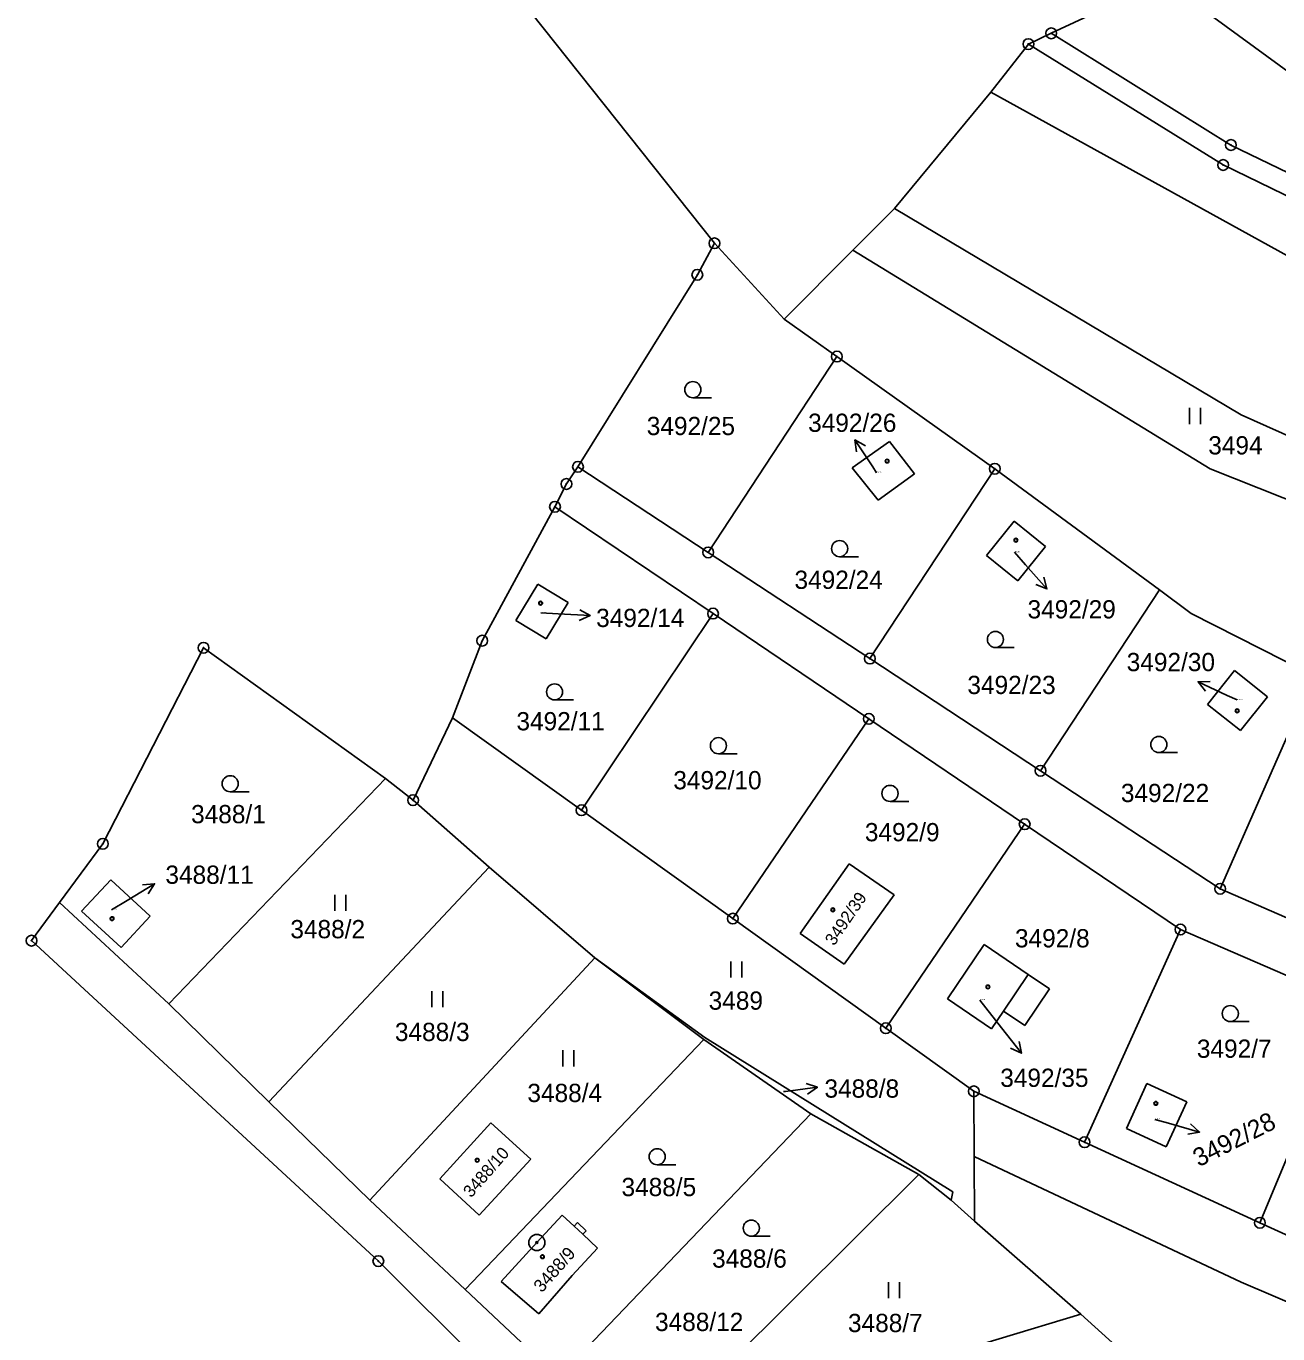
# Model space of a CAD drawing. Extents: x -593183 to -588034, y -1130415 to -1124994.
# Drawn here: x -592836.2 to -592719.7, y -1129035.2 to -1128913.5 of the extents above; entities that cross this region are included whole.
import ezdxf

# ---------------------------------------------------------------- set-up
doc = ezdxf.new("R2010")
doc.units = 0
for name, color, linetype in [('Vrstva 1', 7, 'Continuous'), ('Vrstva 16', 7, 'Continuous'), ('Vrstva 18', 7, 'Continuous'), ('Vrstva 19', 7, 'Continuous'), ('Vrstva 24', 7, 'Continuous'), ('Vrstva 25', 7, 'Continuous'), ('Vrstva 4', 7, 'Continuous')]:
    doc.layers.add(name, color=color, linetype=linetype)

msp = doc.modelspace()

# ---------------------------------------------------------------- linework, layer by layer
at = {"layer": 'Vrstva 1'}
for p, q in [((-592792.9, -1128907.62), (-592772.18, -1128933.7)), ((-592730.37, -1128909.25), (-592740.83, -1128914.15)), ((-592730.37, -1128909.25), (-592713.31, -1128921.75)), ((-592740.83, -1128914.15), (-592742.96, -1128915.15)), ((-592740.83, -1128914.15), (-592724.11, -1128924.55)), ((-592746.46, -1128919.64), (-592742.96, -1128915.15)), ((-592742.96, -1128915.15), (-592724.83, -1128926.41)), ((-592755.43, -1128930.45), (-592746.46, -1128919.64)), ((-592746.46, -1128919.64), (-592718.85, -1128934.87)), ((-592724.11, -1128924.55), (-592695.06, -1128938.62)), ((-592724.83, -1128926.41), (-592695.79, -1128940.49)), ((-592759.3, -1128934.34), (-592755.43, -1128930.45)), ((-592755.43, -1128930.45), (-592723.17, -1128949.66)), ((-592772.18, -1128933.7), (-592773.77, -1128936.63)), ((-592772.18, -1128933.7), (-592765.68, -1128940.75)), ((-592765.68, -1128940.75), (-592759.3, -1128934.34)), ((-592759.3, -1128934.34), (-592726.03, -1128954.69)), ((-592773.77, -1128936.63), (-592784.88, -1128954.51)), ((-592765.68, -1128940.75), (-592760.78, -1128944.25)), ((-592760.78, -1128944.25), (-592772.76, -1128962.48)), ((-592760.78, -1128944.25), (-592746.09, -1128954.69)), ((-592723.17, -1128949.66), (-592691.23, -1128964.05)), ((-592755.89, -1128952.17), (-592759.37, -1128954.61)), ((-592753.55, -1128955.16), (-592755.89, -1128952.17)), ((-592784.88, -1128954.51), (-592785.96, -1128956.11)), ((-592772.76, -1128962.48), (-592784.88, -1128954.51)), ((-592759.37, -1128954.61), (-592756.95, -1128957.63)), ((-592746.09, -1128954.69), (-592757.71, -1128972.37)), ((-592746.09, -1128954.69), (-592730.76, -1128965.97)), ((-592726.03, -1128954.69), (-592694.14, -1128967.46)), ((-592756.95, -1128957.63), (-592753.55, -1128955.16)), ((-592787.02, -1128958.23), (-592785.96, -1128956.11)), ((-592793.79, -1128970.7), (-592787.02, -1128958.23)), ((-592787.02, -1128958.23), (-592772.31, -1128968.18)), ((-592746.85, -1128962.77), (-592744.27, -1128959.58)), ((-592744.27, -1128959.58), (-592741.36, -1128961.94)), ((-592741.36, -1128961.94), (-592743.93, -1128965.13)), ((-592757.71, -1128972.37), (-592772.76, -1128962.48)), ((-592743.93, -1128965.13), (-592746.85, -1128962.77)), ((-592788.62, -1128965.45), (-592790.65, -1128968.82)), ((-592785.8, -1128967.15), (-592788.62, -1128965.45)), ((-592730.76, -1128965.97), (-592741.83, -1128982.81)), ((-592730.76, -1128965.97), (-592727.81, -1128968.16)), ((-592787.83, -1128970.52), (-592785.8, -1128967.15)), ((-592790.65, -1128968.82), (-592787.83, -1128970.52)), ((-592772.31, -1128968.18), (-592784.55, -1128986.49)), ((-592772.31, -1128968.18), (-592757.81, -1128977.98)), ((-592727.81, -1128968.16), (-592716.41, -1128973.96)), ((-592829.1, -1128989.61), (-592819.73, -1128971.36)), ((-592819.73, -1128971.36), (-592802.81, -1128983.54)), ((-592793.79, -1128970.7), (-592796.57, -1128977.87)), ((-592741.83, -1128982.81), (-592757.71, -1128972.37)), ((-592726.28, -1128976.63), (-592723.78, -1128973.48)), ((-592716.41, -1128973.96), (-592725.11, -1128993.8)), ((-592723.78, -1128973.48), (-592720.71, -1128975.92)), ((-592723.21, -1128979.07), (-592726.28, -1128976.63)), ((-592720.71, -1128975.92), (-592723.21, -1128979.07)), ((-592800.23, -1128985.55), (-592796.57, -1128977.87)), ((-592796.57, -1128977.87), (-592784.55, -1128986.49)), ((-592757.81, -1128977.98), (-592770.47, -1128996.58)), ((-592757.81, -1128977.98), (-592743.31, -1128987.79)), ((-592802.81, -1128983.54), (-592822.97, -1129004.51)), ((-592802.81, -1128983.54), (-592800.23, -1128985.55)), ((-592741.83, -1128982.81), (-592725.11, -1128993.8)), ((-592800.23, -1128985.55), (-592793.15, -1128991.79)), ((-592784.55, -1128986.49), (-592770.47, -1128996.58)), ((-592743.31, -1128987.79), (-592756.23, -1129006.79)), ((-592743.31, -1128987.79), (-592728.81, -1128997.59)), ((-592833.15, -1128995.08), (-592829.1, -1128989.61)), ((-592813.65, -1129013.64), (-592793.15, -1128991.79)), ((-592793.15, -1128991.79), (-592783.3, -1129000.23)), ((-592764.2, -1128997.96), (-592759.64, -1128991.47)), ((-592759.64, -1128991.47), (-592755.44, -1128994.35)), ((-592831.08, -1128995.89), (-592828.37, -1128992.96)), ((-592828.37, -1128992.96), (-592824.7, -1128996.34)), ((-592755.44, -1128994.35), (-592760.11, -1129000.83)), ((-592725.11, -1128993.8), (-592708.62, -1129001.03)), ((-592833.15, -1128995.08), (-592835.74, -1128998.63)), ((-592822.97, -1129004.51), (-592833.15, -1128995.08)), ((-592827.39, -1128999.26), (-592831.08, -1128995.89)), ((-592824.7, -1128996.34), (-592827.39, -1128999.26)), ((-592770.47, -1128996.58), (-592756.23, -1129006.79)), ((-592760.11, -1129000.83), (-592764.2, -1128997.96)), ((-592737.73, -1129017.4), (-592728.81, -1128997.59)), ((-592728.81, -1128997.59), (-592712.93, -1129004.46)), ((-592835.74, -1128998.63), (-592803.46, -1129028.47)), ((-592750.5, -1129004.06), (-592747.08, -1128999)), ((-592747.08, -1128999), (-592742.97, -1129001.78)), ((-592783.3, -1129000.23), (-592804.24, -1129022.81)), ((-592773.16, -1129007.85), (-592783.3, -1129000.23)), ((-592783.3, -1129000.23), (-592773.06, -1129007.65)), ((-592742.97, -1129001.78), (-592740.99, -1129003.11)), ((-592740.99, -1129003.11), (-592743.29, -1129006.53)), ((-592822.97, -1129004.51), (-592813.65, -1129013.64)), ((-592746.38, -1129006.84), (-592750.5, -1129004.06)), ((-592712.93, -1129004.46), (-592721.41, -1129024.9)), ((-592745.27, -1129005.19), (-592746.38, -1129006.84)), ((-592743.29, -1129006.53), (-592745.27, -1129005.19)), ((-592756.23, -1129006.79), (-592748.04, -1129012.66)), ((-592795.38, -1129031.11), (-592773.16, -1129007.85)), ((-592773.16, -1129007.85), (-592763.22, -1129014.75)), ((-592773.06, -1129007.65), (-592750, -1129022.01)), ((-592733.84, -1129016.11), (-592731.93, -1129011.94)), ((-592731.93, -1129011.94), (-592728.21, -1129013.65)), ((-592748.04, -1129012.66), (-592737.73, -1129017.4)), ((-592748, -1129018.74), (-592748.04, -1129012.66)), ((-592804.24, -1129022.81), (-592813.65, -1129013.64)), ((-592728.21, -1129013.65), (-592730.13, -1129017.82)), ((-592797.75, -1129020.8), (-592792.98, -1129015.58)), ((-592792.98, -1129015.58), (-592789.27, -1129018.98)), ((-592763.22, -1129014.75), (-592786.68, -1129039.27)), ((-592763.22, -1129014.75), (-592753.15, -1129020.41)), ((-592730.13, -1129017.82), (-592733.84, -1129016.11)), ((-592737.73, -1129017.4), (-592721.41, -1129024.9)), ((-592789.27, -1129018.98), (-592794.07, -1129024.2)), ((-592748, -1129018.74), (-592747.99, -1129024.74)), ((-592748, -1129018.74), (-592723.17, -1129030.44)), ((-592778.43, -1129045.55), (-592753.15, -1129020.41)), ((-592753.15, -1129020.41), (-592750.15, -1129022.78)), ((-592794.07, -1129024.2), (-592797.75, -1129020.8)), ((-592804.24, -1129022.81), (-592795.38, -1129031.11)), ((-592750, -1129022.01), (-592750.15, -1129022.78)), ((-592750.15, -1129022.78), (-592747.99, -1129024.74)), ((-592788.71, -1129026.74), (-592786.34, -1129024.2)), ((-592786.34, -1129024.2), (-592785.24, -1129025.22)), ((-592785.24, -1129025.22), (-592784.94, -1129024.89)), ((-592784.94, -1129024.89), (-592784.13, -1129025.64)), ((-592747.99, -1129024.74), (-592738.08, -1129033.41)), ((-592704.97, -1129032.46), (-592721.41, -1129024.9)), ((-592784.13, -1129025.64), (-592784.44, -1129025.97)), ((-592784.44, -1129025.97), (-592783.05, -1129027.27)), ((-592788.71, -1129026.74), (-592792.02, -1129030.36)), ((-592783.05, -1129027.27), (-592785.42, -1129029.81)), ((-592803.46, -1129028.47), (-592784.63, -1129047.23)), ((-592788.54, -1129033.38), (-592785.42, -1129029.81)), ((-592786.68, -1129039.27), (-592795.38, -1129031.11)), ((-592792.02, -1129030.36), (-592788.54, -1129033.38)), ((-592723.17, -1129030.44), (-592709.6, -1129036.24)), ((-592738.08, -1129033.41), (-592778.43, -1129045.55)), ((-592738.08, -1129033.41), (-592734.83, -1129036.37))]:
    msp.add_line(p, q, dxfattribs=at)
at = {"layer": 'Vrstva 16'}
for p, q in [((-592757.09, -1128955.06), (-592757.45, -1128954.51)), ((-592744.25, -1128962.46), (-592743.22, -1128963.63)), ((-592788.33, -1128968.12), (-592786.74, -1128968.21)), ((-592723.52, -1128976.22), (-592724.45, -1128975.79)), ((-592828.29, -1128995.76), (-592826.85, -1128994.89)), ((-592747.48, -1129004.17), (-592745.46, -1129006.75)), ((-592765.75, -1129012.69), (-592765.57, -1129012.67)), ((-592731.19, -1129015.27), (-592729.92, -1129015.63))]:
    msp.add_line(p, q, dxfattribs=at)
at = {"layer": 'Vrstva 24'}
for centre, radius in [((-592740.83, -1128914.15), 0.5), ((-592740.83, -1128914.15), 0.0327), ((-592742.96, -1128915.15), 0.5), ((-592742.96, -1128915.15), 0.0327), ((-592724.11, -1128924.55), 0.5), ((-592724.11, -1128924.55), 0.0327), ((-592724.83, -1128926.41), 0.5), ((-592724.83, -1128926.41), 0.0327), ((-592772.18, -1128933.7), 0.5), ((-592772.18, -1128933.7), 0.0327), ((-592773.77, -1128936.63), 0.5), ((-592773.77, -1128936.63), 0.0327), ((-592760.78, -1128944.25), 0.5), ((-592760.78, -1128944.25), 0.0327), ((-592784.88, -1128954.51), 0.5), ((-592784.88, -1128954.51), 0.0327), ((-592746.09, -1128954.69), 0.5), ((-592746.09, -1128954.69), 0.0327), ((-592785.96, -1128956.11), 0.5), ((-592785.96, -1128956.11), 0.0327), ((-592787.02, -1128958.23), 0.5), ((-592787.02, -1128958.23), 0.0327), ((-592772.76, -1128962.48), 0.5), ((-592772.76, -1128962.48), 0.0327), ((-592772.31, -1128968.18), 0.5), ((-592772.31, -1128968.18), 0.0327), ((-592793.79, -1128970.7), 0.5), ((-592819.73, -1128971.36), 0.5), ((-592819.73, -1128971.36), 0.0327), ((-592793.79, -1128970.7), 0.0327), ((-592757.71, -1128972.37), 0.5), ((-592757.71, -1128972.37), 0.0327), ((-592757.81, -1128977.98), 0.5), ((-592757.81, -1128977.98), 0.0327), ((-592741.83, -1128982.81), 0.5), ((-592741.83, -1128982.81), 0.0327), ((-592800.23, -1128985.55), 0.5), ((-592800.23, -1128985.55), 0.0327), ((-592784.55, -1128986.49), 0.5), ((-592784.55, -1128986.49), 0.0327), ((-592743.31, -1128987.79), 0.5), ((-592743.31, -1128987.79), 0.0327), ((-592829.1, -1128989.61), 0.5), ((-592829.1, -1128989.61), 0.0327), ((-592725.11, -1128993.8), 0.5), ((-592725.11, -1128993.8), 0.0327), ((-592770.47, -1128996.58), 0.5), ((-592770.47, -1128996.58), 0.0327), ((-592728.81, -1128997.59), 0.5), ((-592835.74, -1128998.63), 0.5), ((-592728.81, -1128997.59), 0.0327), ((-592835.74, -1128998.63), 0.0327), ((-592756.23, -1129006.79), 0.5), ((-592756.23, -1129006.79), 0.0327), ((-592748.04, -1129012.66), 0.5), ((-592748.04, -1129012.66), 0.0327), ((-592737.73, -1129017.4), 0.5), ((-592737.73, -1129017.4), 0.0327), ((-592721.41, -1129024.9), 0.5), ((-592721.41, -1129024.9), 0.0327), ((-592788.71, -1129026.74), 0.75), ((-592788.71, -1129026.74), 0.0903), ((-592803.46, -1129028.47), 0.5), ((-592803.46, -1129028.47), 0.0327)]:
    msp.add_circle(centre, radius, dxfattribs=at)
at = {"layer": 'Vrstva 25'}
for p, q in [((-592772.44, -1128948.08), (-592774.19, -1128948.08)), ((-592727.97, -1128949.03), (-592727.97, -1128950.53)), ((-592726.95, -1128950.53), (-592726.95, -1128949.03)), ((-592757.45, -1128954.51), (-592759.1, -1128952.01)), ((-592758.78, -1128962.88), (-592760.53, -1128962.88)), ((-592743.22, -1128963.63), (-592741.23, -1128965.88)), ((-592786.74, -1128968.21), (-592783.74, -1128968.37)), ((-592744.28, -1128971.34), (-592746.03, -1128971.34)), ((-592724.45, -1128975.79), (-592727.17, -1128974.52)), ((-592785.31, -1128976.22), (-592787.06, -1128976.22)), ((-592770.06, -1128981.23), (-592771.81, -1128981.23)), ((-592729.07, -1128981.12), (-592730.82, -1128981.12)), ((-592815.5, -1128984.77), (-592817.25, -1128984.77)), ((-592754.09, -1128985.67), (-592755.84, -1128985.67)), ((-592826.85, -1128994.89), (-592824.28, -1128993.34)), ((-592807.51, -1128994.36), (-592807.51, -1128995.86)), ((-592806.48, -1128995.86), (-592806.48, -1128994.36)), ((-592770.65, -1129000.56), (-592770.65, -1129002.06)), ((-592769.62, -1129002.06), (-592769.62, -1129000.56)), ((-592798.47, -1129003.32), (-592798.47, -1129004.82)), ((-592797.45, -1129004.82), (-592797.45, -1129003.32)), ((-592745.46, -1129006.75), (-592743.61, -1129009.11)), ((-592722.42, -1129006.17), (-592724.17, -1129006.17)), ((-592786.3, -1129008.84), (-592786.3, -1129010.34)), ((-592785.28, -1129010.34), (-592785.28, -1129008.84)), ((-592765.57, -1129012.67), (-592762.59, -1129012.28)), ((-592729.92, -1129015.63), (-592727.03, -1129016.45)), ((-592775.76, -1129019.5), (-592777.51, -1129019.5)), ((-592767, -1129026.15), (-592768.75, -1129026.15)), ((-592755.97, -1129030.43), (-592755.97, -1129031.93)), ((-592754.95, -1129031.93), (-592754.95, -1129030.43))]:
    msp.add_line(p, q, dxfattribs=at)
for points in [[(-592758.97, -1128953.12), (-592759.1, -1128952.01), (-592758.13, -1128952.56)], [(-592741.52, -1128964.8), (-592741.23, -1128965.88), (-592742.27, -1128965.46)], [(-592784.72, -1128967.82), (-592783.74, -1128968.37), (-592784.77, -1128968.82)], [(-592726.47, -1128975.4), (-592727.17, -1128974.52), (-592726.05, -1128974.49)], [(-592825.4, -1128993.43), (-592824.28, -1128993.34), (-592824.88, -1128994.28)], [(-592743.83, -1129008.02), (-592743.61, -1129009.11), (-592744.62, -1129008.63)], [(-592763.65, -1129011.92), (-592762.59, -1129012.28), (-592763.52, -1129012.91)], [(-592727.86, -1129015.69), (-592727.03, -1129016.45), (-592728.13, -1129016.66)]]:
    msp.add_lwpolyline(points, dxfattribs=at)
for centre, radius in [((-592774.19, -1128947.33), 0.75), ((-592756.11, -1128953.98), 0.175), ((-592756.11, -1128953.98), 0.15), ((-592760.53, -1128962.13), 0.75), ((-592744.12, -1128961.34), 0.175), ((-592744.12, -1128961.34), 0.15), ((-592788.36, -1128967.21), 0.175), ((-592788.36, -1128967.21), 0.15), ((-592746.03, -1128970.59), 0.75), ((-592787.06, -1128975.47), 0.75), ((-592723.53, -1128977.23), 0.175), ((-592723.53, -1128977.23), 0.15), ((-592771.81, -1128980.48), 0.75), ((-592730.82, -1128980.37), 0.75), ((-592817.25, -1128984.02), 0.75), ((-592755.84, -1128984.92), 0.75), ((-592761.16, -1128995.76), 0.175), ((-592761.16, -1128995.76), 0.15), ((-592828.25, -1128996.58), 0.175), ((-592828.25, -1128996.58), 0.15), ((-592746.73, -1129002.94), 0.175), ((-592746.73, -1129002.94), 0.15), ((-592724.17, -1129005.42), 0.75), ((-592731.1, -1129013.78), 0.175), ((-592731.1, -1129013.78), 0.15), ((-592777.51, -1129018.75), 0.75), ((-592794.26, -1129019.08), 0.175), ((-592794.26, -1129019.08), 0.15), ((-592768.75, -1129025.4), 0.75), ((-592788.19, -1129028.06), 0.175), ((-592788.19, -1129028.06), 0.15)]:
    msp.add_circle(centre, radius, dxfattribs=at)
at = {"layer": 'Vrstva 4'}
for p, q in [((-592745.27, -1129005.19), (-592742.97, -1129001.78)), ((-592785.24, -1129025.22), (-592784.44, -1129025.97))]:
    msp.add_line(p, q, dxfattribs=at)

# ---------------------------------------------------------------- texts
at = {"layer": 'Vrstva 16'}
for s, p in [('3492/26', (-592763.46, -1128951.26)), ('3492/29', (-592743.04, -1128968.63)), ('3492/14', (-592783.19, -1128969.43)), ('3492/30', (-592733.81, -1128973.54)), ('3488/11', (-592823.28, -1128993.34)), ('3492/35', (-592745.58, -1129012.25)), ('3488/8', (-592761.94, -1129013.25)), ('3488/12', (-592777.71, -1129034.98))]:
    msp.add_text(s, height=1.7, dxfattribs=at).set_placement(p)
msp.add_text('3492/28', height=1.7, rotation=26.8825, dxfattribs=at).set_placement((-592727.1, -1129019.74))
at = {"layer": 'Vrstva 18'}
for s, height, p in [('3492/25', 1.7, (-592778.48, -1128951.56)), ('3494', 1.7, (-592726.22, -1128953.36)), ('3492/24', 1.7, (-592764.73, -1128965.88)), ('3492/23', 1.7, (-592748.64, -1128975.67)), ('3492/11', 1.7, (-592790.61, -1128979.05)), ('3492/10', 1.7, (-592776.01, -1128984.54)), ('3492/22', 1.7, (-592734.35, -1128985.73)), ('3488/1', 1.7, (-592820.89, -1128987.7)), ('3492/9', 1.7, (-592758.18, -1128989.38)), ('3488/2', 1.7, (-592811.65, -1128998.41)), ('3492/8', 1.7, (-592744.21, -1128999.26)), ('3489', 1.7, (-592772.72, -1129005.06)), ('3488/3', 1.7, (-592801.92, -1129007.98)), ('3492/7', 1.7, (-592727.28, -1129009.54)), ('3488/4', 1.7, (-592789.59, -1129013.66)), ('3488/8', 0.1, (-592765.75, -1129012.69)), ('3488/5', 1.7, (-592780.83, -1129022.42)), ('3488/6', 1.7, (-592772.4, -1129029.08)), ('3488/7', 1.7, (-592759.75, -1129035.08))]:
    msp.add_text(s, height=height, dxfattribs=at).set_placement(p)
at = {"layer": 'Vrstva 19'}
for s, p in [('3492/26', (-592757.09, -1128955.06)), ('3492/29', (-592744.25, -1128962.46)), ('3492/14', (-592788.33, -1128968.12)), ('3492/30', (-592723.52, -1128976.22)), ('3488/11', (-592828.29, -1128995.76)), ('3492/35', (-592747.48, -1129004.17)), ('3492/28', (-592731.19, -1129015.27))]:
    msp.add_text(s, height=0.1, dxfattribs=at).set_placement(p)
for s, height, rotation, p in [('3492/39', 1.14, 55.7752, (-592761.04, -1128999.17)), ('3488/10', 1.14, 48.9542, (-592794.82, -1129022.63)), ('3488/9', 1.19, 48.6913, (-592788.24, -1129031.47))]:
    msp.add_text(s, height=height, rotation=rotation, dxfattribs=at).set_placement(p)

doc.saveas('drawing.dxf')
